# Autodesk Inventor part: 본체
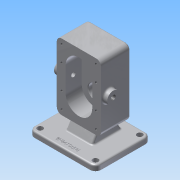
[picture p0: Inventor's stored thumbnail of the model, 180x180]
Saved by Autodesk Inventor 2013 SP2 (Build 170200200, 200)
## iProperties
Created: 2026-10
Part Number: 본체
Material: 알루미늄 6061
Document SubType Name: Modeling
Designer: a
Density: 2.71 g/cm^3
Mass: 1478.92 g
Surface Area: 823.005 cm^2
Volume: 545.726 cm^3
Author: a
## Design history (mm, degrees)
sketch "스케치1"
  geometry: L1 (-31, -60)-(31, -60); L2 (40, -51)-(40, 51); L3 (31, 60)-(-31, 60); L4 (-40, 51)-(-40, -51); L5 (-40, -60)-(40, 60); L6 (40, -60)-(-40, 60); A1 r 9 centre (-31, 51) between (-31, 60) and (-40, 51); A2 r 9 centre (31, 51) between (40, 51) and (31, 60); A3 r 9 centre (31, -51) between (31, -60) and (40, -51); A4 r 9 centre (-31, -51) between (-40, -51) and (-31, -60); 1 further point
  constraints: 12 end point, 8 point on circle, 8 point on line, 8 tangent, 4 centre point, 2 midpoint, 2 parallel, 1 horizontal, 1 perpendicular
  dimensions: "d0" = 80 distance of L5.end L6.end; "d2" = 120 distance of L6.start L5.end; "d3" = 9 radius of A1; "d4" = 9 radius of A2; "d5" = 9 radius of A3; "d6" = 9 radius of A4
extrude "돌출1" new body sketch "스케치1" distance "d7" = 53; taper "d8" = 0 deg
sketch "스케치2"
  geometry: L1 (0, -46)-(0, -46); L2 (24, -22)-(24, 22); L3 (0, 46)-(0, 46); L4 (-24, 22)-(-24, -22); L5 (-24, -46)-(24, 46); L6 (24, -46)-(-24, 46); A1 r 24 centre (0, 22) between (0, 46) and (-24, 22); A2 r 24 centre (0, 22) between (24, 22) and (0, 46); A3 r 24 centre (0, -22) between (0, -46) and (24, -22); A4 r 24 centre (0, -22) between (-24, -22) and (0, -46); 1 further point
  constraints: 12 end point, 8 point on circle, 8 point on line, 8 tangent, 4 centre point, 2 midpoint, 2 parallel, 1 horizontal, 1 perpendicular
  dimensions: "d9" = 48 distance of L5.end L6.end; "d11" = 24 radius of A1; "d12" = 24 radius of A2; "d13" = 24 radius of A3; "d14" = 24 radius of A4; "d15" = 44 distance of A3.centre A2.centre
extrude "돌출2" cut sketch "스케치2" distance "d16" = 29; taper "d17" = 0 deg
sketch "스케치3"
  geometry: C1 r 19.02 at (0, 22); 1 further point
  constraints: 1 centre point, 1 vertical alignment
  dimensions: "d18" = 22 distance of point (0, 0) C1.centre
extrude "돌출3" join sketch "스케치3" distance "d19" = 17; taper "d20" = 0 deg
sketch "스케치4"
  geometry: L1 (60, 0)-(60, -53) reference; L2 (60, -53)-(41.02, -53) reference; L3 (41.02, -53)-(41.02, -70) reference; L4 (41.02, -70)-(2.98, -70) reference; L5 (2.98, -70)-(2.98, -53) reference; L6 (2.98, -53)-(-60, -53) reference; L7 (-60, -53)-(-60, 0) reference; L8 (-60, 0)-(-46, 0) reference; L9 (-46, 0)-(-46, -29) reference; L10 (-46, -29)-(46, -29) reference; L11 (46, -29)-(46, 0) reference; L12 (46, 0)-(60, 0) reference; L13 (22, -70)-(22, -29); L14 (22, -29)-(34.5, -29); L15 (34.5, -29)-(34.5, -44); L16 (34.5, -44)-(30.5, -44); L17 (30.5, -44)-(30.5, -62.7); L18 (30.5, -62.7)-(36, -62.7); L19 (36, -62.7)-(36, -70); L20 (22, -70)-(36, -70); 1 further point
  constraints: 16 end point, 4 perpendicular, 3 parallel, 3 point on line, 1 midpoint
  dimensions: "d21" = 15 distance of L14.end L15.end; "d23" = 7.3 distance of L18.end L19.end; "d24" = 25 diameter of L15 L13; "d25" = 17 diameter of L17 L13; "d26" = 28 diameter of L19 L13
revolve "회전1" sketch "스케치4" stored, may be unused: angle "d27" = 90 deg
sketch "스케치5"
  geometry: C1 r 12.5 at (0, -22); A1 r 24 centre (0, -22) between (-24, -22) and (24, -22) reference; 1 further point
  constraints: 1 centre point, 1 coincident
  dimensions: "d28" = 25 diameter of C1
extrude "돌출4" cut sketch "스케치5" distance "d30" = 15; taper "d31" = 0 deg
sketch "스케치6"
  geometry: L1 (0, 102)-(0, 0) reference; C1 r 11 at (14, 51); 2 further points
  constraints: 1 centre point, 1 horizontal alignment, 1 midpoint
  dimensions: "d32" = 22 diameter of C1; "d34" = 14 distance of point (0, 51) C1.centre
extrude "돌출5" join sketch "스케치6" distance "d35" = 8; taper "d36" = 0 deg
sketch "스케치7"
  geometry: L1 (0, 0)-(0, 102) reference; C1 r 11 at (-14, 51); 2 further points
  constraints: 1 centre point, 1 horizontal alignment, 1 midpoint
  dimensions: "d37" = 22 diameter of C1; "d39" = 14 distance of point (0, 51) C1.centre
extrude "돌출6" join sketch "스케치7" distance "d40" = 8; taper "d41" = 0 deg
sketch "스케치8"
  geometry: C1 r 11 at (0, 0) reference; 2 further points
  constraints: 1 coincident
hole "구멍1" sketch "스케치8" at (0, 0) diameter "d42" = 8; stored, may be unused: countersink angle "d48" = 90 deg, drill point angle "d50" = 118 deg; dims "d43" = 9, "d44" = 0.62479, "d45" = 7.985, "d46" = 4, "d47" = 2, "d49" = 8
sketch "스케치9"
  geometry: C1 r 11 at (0, 0) reference; 2 further points
  constraints: 1 coincident
hole "구멍2" sketch "스케치9" at (0, 0) diameter "d51" = 8; stored, may be unused: countersink angle "d57" = 90 deg, drill point angle "d59" = 118 deg; dims "d52" = 9, "d53" = 0.62479, "d54" = 7.985, "d55" = 4, "d56" = 2, "d58" = 8
sketch "스케치10"
  geometry: A1 r 24 centre (0, 22) between (24, 22) and (-24, 22) reference; A2 r 24 centre (0, -22) between (-24, -22) and (24, -22) reference; A3 r 9 centre (-31, 51) between (-31, 60) and (-40, 51) reference; A4 r 9 centre (-31, -51) between (-40, -51) and (-31, -60) reference; A5 r 9 centre (31, -51) between (31, -60) and (40, -51) reference; A6 r 9 centre (31, 51) between (40, 51) and (31, 60) reference; 9 further points
  constraints: 4 coincident, 4 horizontal alignment
hole "구멍3" sketch "스케치10" at (-31, 51), (31, 51), (-31, -51), (31, -51), (-31, 22), (31, 22), (-31, -22), (31, -22) diameter "d60" = 4.134; stored, may be unused: countersink angle "d64" = 90 deg, drill point angle "d66" = 118 deg; dims "d61" = 10, "d62" = 4, "d63" = 2, "d65" = 12
chamfer "모따기1" distance "d67" = 1; stored, may be unused: second distance "d68" = 2, angle "d69" = 45 deg
chamfer "모따기2" distance "d70" = 1; stored, may be unused: second distance "d71" = 2, angle "d72" = 45 deg
node "작업 평면1"
sketch "스케치12"
  geometry: L1 (-19, -30)-(81, -30); L2 (91, -20)-(91, 60); L3 (81, 70)-(-19, 70); L4 (-29, 60)-(-29, -20); L5 (0, 0)-(62, 0) reference; L6 (50.02, 70)-(11.98, 70) reference; A1 r 10 centre (-19, -20) between (-29, -20) and (-19, -30); A2 r 10 centre (-19, 60) between (-19, 70) and (-29, 60); A3 r 10 centre (81, 60) between (91, 60) and (81, 70); A4 r 10 centre (81, -20) between (81, -30) and (91, -20); 4 further points
  constraints: 8 end point, 8 point on circle, 8 tangent, 6 point on line, 4 centre point, 2 parallel, 1 collinear, 1 horizontal, 1 perpendicular
  dimensions: "d75" = 100 distance of point (-29, 70) point (-29, -30); "d77" = 120 distance of point (-29, -30) point (91, -30); "d78" = 60 distance from line of point (31, 0) L4; "d79" = 10 radius of A1; "d80" = 10 radius of A2; "d81" = 10 radius of A3; "d82" = 10 radius of A4
extrude "돌출7" join sketch "스케치12" distance "d83" = 10; taper "d84" = 0 deg
sketch "스케치14"
  geometry: L1 (-60, -53)-(-60, 0) reference; L2 (-60, 0)-(-46, 0) reference; L3 (-46, 0)-(-46, -29) reference; L4 (-46, -29)-(-35.5, -29) reference; L5 (-35.5, -29)-(-34.5, -30) reference; L6 (-34.5, -30)-(-34.5, -44) reference; L7 (-34.5, -44)-(-9.5, -44) reference; L8 (-9.5, -44)-(-9.5, -30) reference; L9 (-9.5, -30)-(-8.5, -29) reference; L10 (-8.5, -29)-(8.5, -29) reference; L11 (8.5, -29)-(9.5, -30) reference; L12 (9.5, -30)-(9.5, -44) reference; L13 (9.5, -44)-(13.5, -44) reference; L14 (13.5, -44)-(13.5, -62.7) reference; L15 (13.5, -62.7)-(8, -62.7) reference; L16 (8, -62.7)-(8, -70) reference; L17 (8, -70)-(2.98, -70) reference; L18 (2.98, -70)-(2.98, -53) reference; L19 (2.98, -53)-(-60, -53) reference; L20 (60, 0)-(60, -53) reference; L21 (60, -53)-(41.02, -53) reference; L22 (41.02, -53)-(41.02, -70) reference; L23 (41.02, -70)-(36, -70) reference; L24 (36, -70)-(36, -62.7) reference; L25 (36, -62.7)-(30.5, -62.7) reference; L26 (30.5, -62.7)-(30.5, -44) reference; L27 (30.5, -44)-(34.5, -44) reference; L28 (34.5, -44)-(34.5, -30) reference; L29 (34.5, -30)-(35.5, -29) reference; L30 (35.5, -29)-(46, -29) reference; L31 (46, -29)-(46, 0) reference; L32 (46, 0)-(60, 0) reference; L33 (-90, 30)-(-80, 30) reference; L34 (-80, 30)-(-80, -70) reference; L35 (-80, -70)-(-90, -70) reference; L36 (-90, -70)-(-90, 30) reference; L37 (-60, -11.547)-(-80, 0); L38 (-60, -41.453)-(-80, -53); L39 (-60, -11.547)-(-60, -41.453); L40 (-80, 0)-(-80, -53); 1 further point
  constraints: 8 end point, 4 point on line, 2 collinear
  dimensions: "d85" = 53 distance of L38.end L37.end; "d86" = 60 deg angle of L34 L38; "d87" = 60 deg angle of L34 L37; "d88" = 17 distance of L34.end L38.end
extrude "돌출8" join sketch "스케치14" stored distance "d89" = 48; taper "d90" = 0 deg
fillet "모깎기2" dims "d91" = 0.5
sketch "스케치15"
  geometry: A1 r 10 centre (81, -20) between (81, -30) and (91, -20) reference; A2 r 10 centre (81, 60) between (91, 60) and (81, 70) reference; A3 r 10 centre (-19, 60) between (-19, 70) and (-29, 60) reference; A4 r 10 centre (-19, -20) between (-29, -20) and (-19, -30) reference; 5 further points
  constraints: 4 coincident
hole "구멍4" sketch "스케치15" at (-19, 60), (81, 60), (-19, -20), (81, -20) diameter "d95" = 10; stored, may be unused: countersink angle "d99" = 90 deg, drill point angle "d101" = 118 deg; dims "d96" = 10, "d97" = 4, "d98" = 2, "d100" = 12
fillet "모깎기3" dims "d102" = 3
fillet "모깎기4" dims "d103" = 3
fillet "모깎기5" dims "d104" = 3
fillet "모깎기6" dims "d105" = 3
fillet "모깎기7" dims "d106" = 3
sketch "스케치16" dims "d0" = 80, "d2" = 120, "d3" = 9, "d4" = 9, "d5" = 9, "d6" = 9
  geometry: L1 (-19, -30)-(81, -30) reference; 2 further points
  constraints: 1 vertical alignment, 1 other
  dimensions: "d108" = 10 distance from line of L1 point (31, -20)
feature "엠보싱1" sketch "스케치16" dims "d0" = 80, "d2" = 120, "d3" = 9, "d4" = 9, "d5" = 9, "d6" = 9, "d9" = 48, "d11" = 24, "d12" = 24, "d13" = 24, "d14" = 24, "d15" = 44, "d109" = 0.5, "d110" = 0
chamfer "모따기4" distance "d111" = 0.7; stored, may be unused: second distance "d112" = 2, angle "d113" = 30 deg
fillet "모깎기8" dims "d114" = 3
node "솔리드1"
node "절단 모서리 투영1"
node "절단 모서리 투영2"
